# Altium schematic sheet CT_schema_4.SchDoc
size 422 x 246 mm
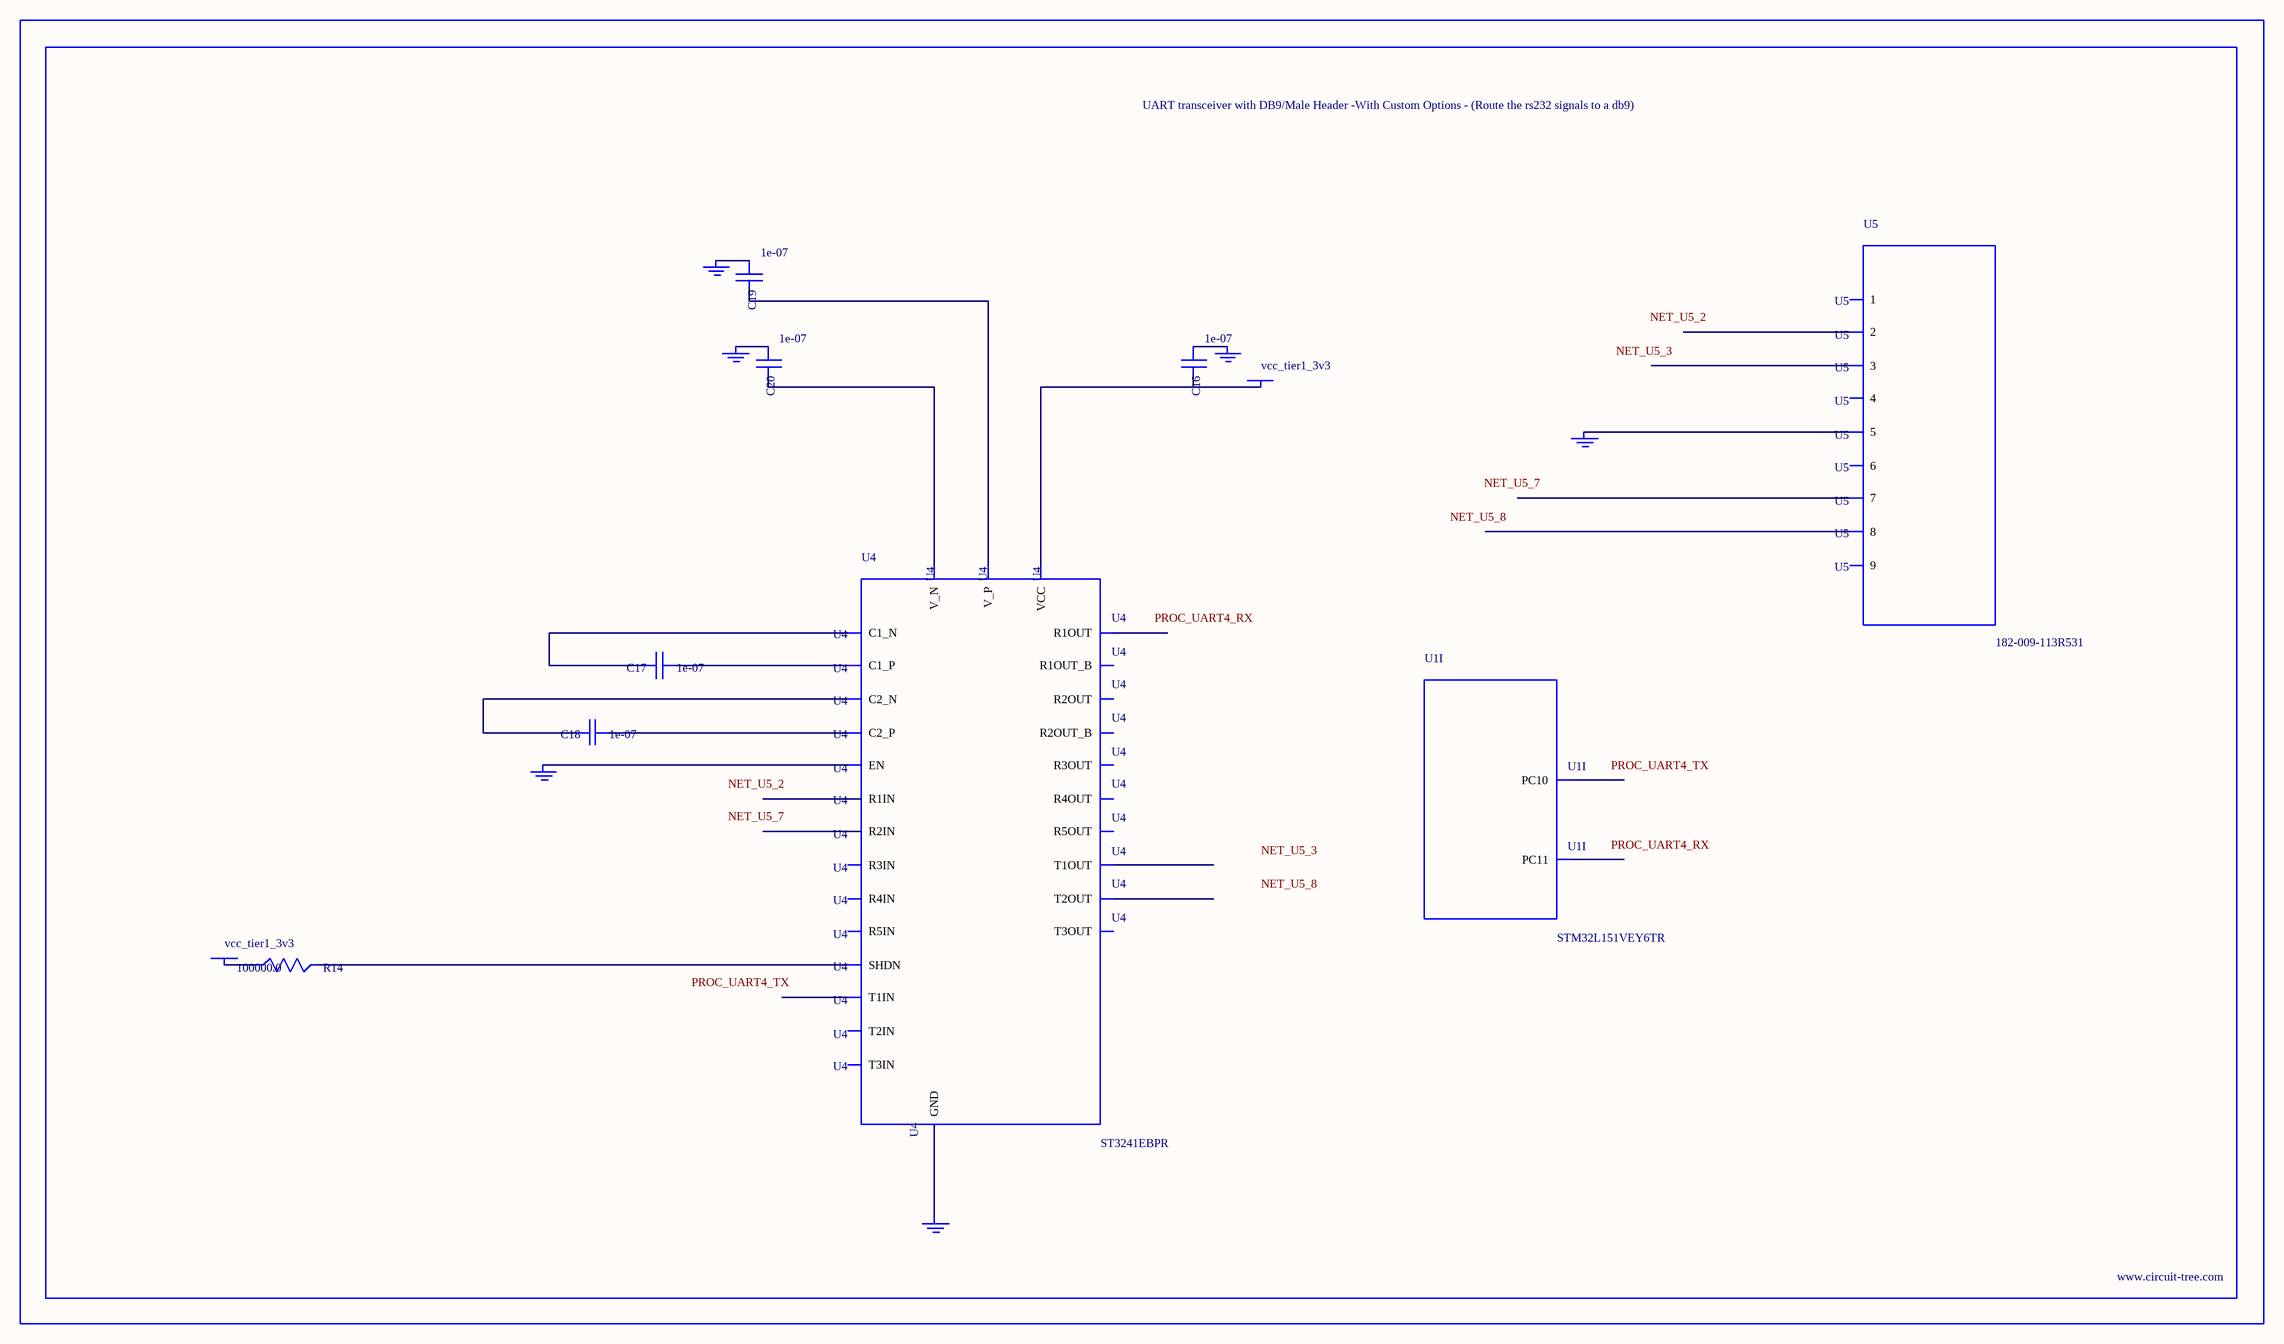
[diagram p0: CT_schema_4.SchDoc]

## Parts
BORDER3  (no value)
C16  1e-07  [C0402]
C17  1e-07  [C0402]
C18  1e-07  [C0402]
C19  1e-07  [C0402]
C20  1e-07  [C0402]
GND_INSTANCE_3_0  (no value)
GND_INSTANCE_3_1  (no value)
GND_INSTANCE_3_2  (no value)
GND_INSTANCE_3_3  (no value)
GND_INSTANCE_3_4  (no value)
GND_INSTANCE_3_5  (no value)
POWER_INSTANCE_3_0  vcc_tier1_3v3
POWER_INSTANCE_3_1  vcc_tier1_3v3
R14  100000.0  [R0603]
U1  STM32L151VEY6TR  [WLCSP104]  (part I of 10)
U4  ST3241EBPR  [SSOP-28]
U5  182-009-113R531  [182-009-MALE]

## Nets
NetC16_1: C16.1 GND_INSTANCE_3_2.0(GND)
NetC16_2: C16.2 POWER_INSTANCE_3_1.0(PWR) U4.26(VCC)
NetC17_1: C17.1 U4.28(C1_P)
NetC17_2: C17.2 U4.24(C1_N)
NetC18_1: C18.1 U4.1(C2_P)
NetC18_2: C18.2 U4.2(C2_N)
NetC19_1: C19.1 GND_INSTANCE_3_3.0(GND)
NetC19_2: C19.2 U4.27(V_P)
NetC20_1: C20.1 GND_INSTANCE_3_0.0(GND)
NetC20_2: C20.2 U4.3(V_N)
NetGND_INSTANCE_3_1_0: GND_INSTANCE_3_1.0(GND) U4.23(EN)
NetGND_INSTANCE_3_4_0: GND_INSTANCE_3_4.0(GND) U4.25(GND)
NetGND_INSTANCE_3_5_0: GND_INSTANCE_3_5.0(GND) U5.5
NetPOWER_INSTANCE_3_0_0: POWER_INSTANCE_3_0.0(PWR) R14.1
NetR14_2: R14.2 U4.22(SHDN)

Not connected (* = marked no-connect by the designer): U1 C2(PC11) E4(PC10); U4 4(R1IN) 5(R2IN) 6(R3IN) 7(R4IN) 8(R5IN) 9(T1OUT) 10(T2OUT) 11(T3OUT) 12(T3IN) 13(T2IN) 14(T1IN) 15(R5OUT) 16(R4OUT) 17(R3OUT) 18(R2OUT) 19(R1OUT) 20(R2OUT_B) 21(R1OUT_B); U5 1 2 3 4 6 7 8 9

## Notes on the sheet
- Labels drawn without touching a wire or pin: NET_U5_2, NET_U5_3, NET_U5_7, NET_U5_8, PROC_UART4_RX, PROC_UART4_TX

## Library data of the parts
BORDER3 = BORDER_PAGE3
C16-C20 = C0402C104K3RACTU
GND_INSTANCE_3_0-GND_INSTANCE_3_5 = GND
POWER_INSTANCE_3_0 POWER_INSTANCE_3_1 = PWR
R14 = RC0603JR-07100KL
